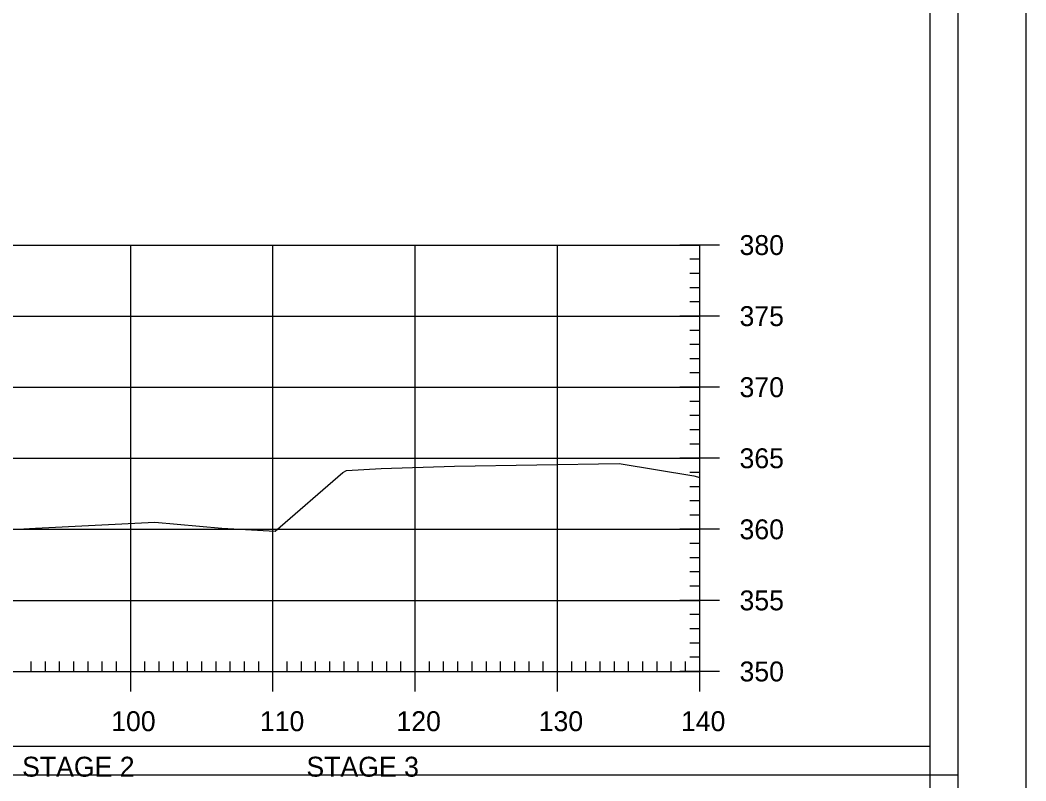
# Model space of a CAD drawing. Extents: x 1368910 to 1369601, y 380116 to 380950.
# Drawn here: x 1369172.5 to 1369243.2, y 380416.7 to 380470.2 of the extents above; entities that cross this region are included whole.
import ezdxf

# ---------------------------------------------------------------- set-up
doc = ezdxf.new("R2010")
doc.units = 0
for name, color, linetype in [('R_Axis', 7, 'Continuous'), ('R_Axis Annot', 7, 'Continuous'), ('R_Border', 7, 'Continuous'), ('R_Border Plan-Plan', 7, 'Continuous'), ('R_Exist Surface', 7, 'Continuous'), ('R_Grid', 7, 'Continuous'), ('R_No Plot', 7, 'Continuous')]:
    doc.layers.add(name, color=color, linetype=linetype)

msp = doc.modelspace()

# ---------------------------------------------------------------- linework, layer by layer
at = {"layer": 'R_Axis'}
for p, q in [((1369221.644, 380454.421), (1369218.844, 380454.421)), ((1369220.244, 380424.421), (1369220.244, 380454.421)), ((1369220.244, 380453.421), (1369219.544, 380453.421)), ((1369220.244, 380452.421), (1369219.544, 380452.421)), ((1369220.244, 380451.421), (1369219.544, 380451.421)), ((1369220.244, 380450.421), (1369219.544, 380450.421)), ((1369221.644, 380449.421), (1369218.844, 380449.421)), ((1369220.244, 380448.421), (1369219.544, 380448.421)), ((1369220.244, 380447.421), (1369219.544, 380447.421)), ((1369220.244, 380446.421), (1369219.544, 380446.421)), ((1369220.244, 380445.421), (1369219.544, 380445.421)), ((1369221.644, 380444.421), (1369218.844, 380444.421)), ((1369220.244, 380443.421), (1369219.544, 380443.421)), ((1369220.244, 380442.421), (1369219.544, 380442.421)), ((1369220.244, 380441.421), (1369219.544, 380441.421)), ((1369220.244, 380440.421), (1369219.544, 380440.421)), ((1369221.644, 380439.421), (1369218.844, 380439.421)), ((1369220.244, 380438.421), (1369219.544, 380438.421)), ((1369220.244, 380437.421), (1369219.544, 380437.421)), ((1369220.244, 380436.421), (1369219.544, 380436.421)), ((1369220.244, 380435.421), (1369219.544, 380435.421)), ((1369221.644, 380434.421), (1369218.844, 380434.421)), ((1369220.244, 380433.421), (1369219.544, 380433.421)), ((1369220.244, 380432.421), (1369219.544, 380432.421)), ((1369220.244, 380431.421), (1369219.544, 380431.421)), ((1369220.244, 380430.421), (1369219.544, 380430.421)), ((1369221.644, 380429.421), (1369218.844, 380429.421)), ((1369220.244, 380428.421), (1369219.544, 380428.421)), ((1369220.244, 380427.421), (1369219.544, 380427.421)), ((1369220.244, 380426.421), (1369219.544, 380426.421)), ((1369180.244, 380423.021), (1369180.244, 380425.821)), ((1369190.244, 380423.021), (1369190.244, 380425.821)), ((1369200.244, 380423.021), (1369200.244, 380425.821)), ((1369210.244, 380423.021), (1369210.244, 380425.821)), ((1369220.244, 380423.021), (1369220.244, 380425.821)), ((1369173.244, 380424.421), (1369173.244, 380425.121)), ((1369174.244, 380424.421), (1369174.244, 380425.121)), ((1369175.244, 380424.421), (1369175.244, 380425.121)), ((1369176.244, 380424.421), (1369176.244, 380425.121)), ((1369177.244, 380424.421), (1369177.244, 380425.121)), ((1369178.244, 380424.421), (1369178.244, 380425.121)), ((1369179.244, 380424.421), (1369179.244, 380425.121)), ((1369181.244, 380424.421), (1369181.244, 380425.121)), ((1369182.244, 380424.421), (1369182.244, 380425.121)), ((1369183.244, 380424.421), (1369183.244, 380425.121)), ((1369184.244, 380424.421), (1369184.244, 380425.121)), ((1369185.244, 380424.421), (1369185.244, 380425.121)), ((1369186.244, 380424.421), (1369186.244, 380425.121)), ((1369187.244, 380424.421), (1369187.244, 380425.121)), ((1369188.244, 380424.421), (1369188.244, 380425.121)), ((1369189.244, 380424.421), (1369189.244, 380425.121)), ((1369191.244, 380424.421), (1369191.244, 380425.121)), ((1369192.244, 380424.421), (1369192.244, 380425.121)), ((1369193.244, 380424.421), (1369193.244, 380425.121)), ((1369194.244, 380424.421), (1369194.244, 380425.121)), ((1369195.244, 380424.421), (1369195.244, 380425.121)), ((1369196.244, 380424.421), (1369196.244, 380425.121)), ((1369197.244, 380424.421), (1369197.244, 380425.121)), ((1369198.244, 380424.421), (1369198.244, 380425.121)), ((1369199.244, 380424.421), (1369199.244, 380425.121)), ((1369201.244, 380424.421), (1369201.244, 380425.121)), ((1369202.244, 380424.421), (1369202.244, 380425.121)), ((1369203.244, 380424.421), (1369203.244, 380425.121)), ((1369204.244, 380424.421), (1369204.244, 380425.121)), ((1369205.244, 380424.421), (1369205.244, 380425.121)), ((1369206.244, 380424.421), (1369206.244, 380425.121)), ((1369207.244, 380424.421), (1369207.244, 380425.121)), ((1369208.244, 380424.421), (1369208.244, 380425.121)), ((1369209.244, 380424.421), (1369209.244, 380425.121)), ((1369211.244, 380424.421), (1369211.244, 380425.121)), ((1369212.244, 380424.421), (1369212.244, 380425.121)), ((1369213.244, 380424.421), (1369213.244, 380425.121)), ((1369214.244, 380424.421), (1369214.244, 380425.121)), ((1369215.244, 380424.421), (1369215.244, 380425.121)), ((1369216.244, 380424.421), (1369216.244, 380425.121)), ((1369217.244, 380424.421), (1369217.244, 380425.121)), ((1369218.244, 380424.421), (1369218.244, 380425.121)), ((1369219.244, 380424.421), (1369219.244, 380425.121)), ((1369220.244, 380425.421), (1369219.544, 380425.421)), ((1368940.244, 380424.421), (1369220.244, 380424.421)), ((1369221.644, 380424.421), (1369218.844, 380424.421))]:
    msp.add_line(p, q, dxfattribs=at)
at = {"layer": 'R_Border'}
msp.add_line((1369238.424, 380314.421), (1369238.424, 380519.881), dxfattribs=at)
at = {"layer": 'R_Border Plan-Plan'}
msp.add_line((1368922.244, 380417.151), (1369238.424, 380417.151), dxfattribs=at)
at = {"layer": 'R_Exist Surface'}
msp.add_lwpolyline([(1369172.303, 380434.435), (1369173.56, 380434.514), (1369181.947, 380434.916), (1369186.641, 380434.506), (1369190.395, 380434.282), (1369195.167, 380438.409), (1369195.412, 380438.565), (1369197.861, 380438.692), (1369202.996, 380438.865), (1369214.582, 380439.045), (1369219.843, 380438.186), (1369220.244, 380438.078)], dxfattribs=at)
at = {"layer": 'R_Grid'}
for p, q in [((1368940.244, 380454.421), (1369220.244, 380454.421)), ((1369180.244, 380424.421), (1369180.244, 380454.421)), ((1369190.244, 380424.421), (1369190.244, 380454.421)), ((1369200.244, 380424.421), (1369200.244, 380454.421)), ((1369210.244, 380424.421), (1369210.244, 380454.421)), ((1369220.244, 380424.421), (1369220.244, 380454.421)), ((1368940.244, 380449.421), (1369220.244, 380449.421)), ((1368940.244, 380444.421), (1369220.244, 380444.421)), ((1368940.244, 380439.421), (1369220.244, 380439.421)), ((1368940.244, 380434.421), (1369220.244, 380434.421)), ((1368940.244, 380429.421), (1369220.244, 380429.421)), ((1368940.244, 380424.421), (1369220.244, 380424.421))]:
    msp.add_line(p, q, dxfattribs=at)
at = {"layer": 'R_No Plot'}
for points in [[(1368909.836, 380523.775), (1369243.176, 380523.775), (1369243.176, 380310.438), (1368909.836, 380310.438)], [(1369236.424, 380419.151), (1368924.244, 380419.151), (1368924.244, 380517.881), (1369173.784, 380517.881), (1369173.784, 380508.001), (1369191.324, 380508.001), (1369215.424, 380508.001), (1369215.424, 380485.668), (1369236.424, 380485.668)], [(1368924.244, 380517.881), (1369173.784, 380517.881), (1369173.784, 380508.001), (1369191.324, 380508.001), (1369215.424, 380508.001), (1369215.424, 380485.668), (1369236.424, 380485.668), (1369236.424, 380316.421), (1368924.244, 380316.421)]]:
    msp.add_lwpolyline(points, close=True, dxfattribs=at)

# ---------------------------------------------------------------- texts
at = {"layer": 'R_Axis Annot'}
for s, p in [('380', (1369223.044, 380453.721)), ('375', (1369223.044, 380448.721)), ('370', (1369223.044, 380443.721)), ('365', (1369223.044, 380438.721)), ('360', (1369223.044, 380433.721)), ('355', (1369223.044, 380428.721)), ('350', (1369223.044, 380423.721)), ('100', (1369178.871, 380420.221)), ('110', (1369189.323, 380420.221)), ('120', (1369198.926, 380420.221)), ('130', (1369208.926, 380420.221)), ('140', (1369218.926, 380420.221)), ('STAGE 2', (1369172.606, 380417.021)), ('STAGE 3', (1369192.596, 380417.021))]:
    msp.add_text(s, height=1.4, dxfattribs=at).set_placement(p)

doc.saveas('drawing.dxf')
